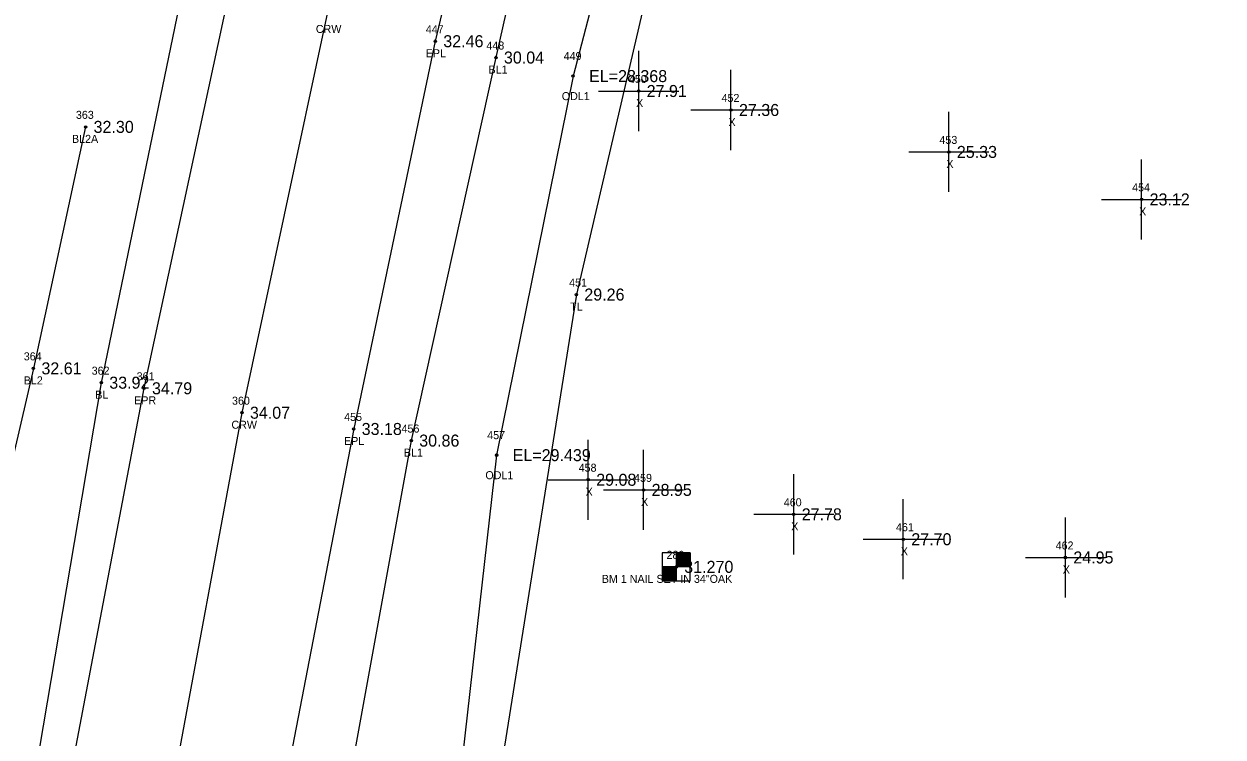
# Model space of a CAD drawing. Extents: x 2042211 to 2045853, y 303080 to 309569.
# Drawn here: x 2042849.9 to 2042999.7, y 307682.5 to 307771.5 of the extents above; entities that cross this region are included whole.
import ezdxf

# ---------------------------------------------------------------- set-up
doc = ezdxf.new("R2010")
doc.units = 0
for name, color, linetype in [('BR_500YR_SCOUR', 7, 'Continuous'), ('RD_DTM_BkLn1', 7, 'Continuous'), ('RD_DTM_BkLn_txCode', 7, 'Continuous'), ('RD_EX_H2O', 7, 'Continuous'), ('RD_EX_H2O_txCode', 7, 'Continuous'), ('RD_EX_Misc', 7, 'Continuous'), ('RD_EX_Misc_txCode', 7, 'Continuous'), ('RD_EX_Road', 7, 'Continuous'), ('RD_EX_Road_txCode', 7, 'Continuous'), ('RD_EX_TX_H2O_ELEV', 7, 'Continuous'), ('RD_EX_TX_Misc_ELEV', 7, 'Continuous'), ('RD_EX_TX_Road_ELEV', 7, 'Continuous'), ('RD_EX_TX_VEG_ELEV', 7, 'Continuous'), ('RD_EX_VEG_txCode', 7, 'Continuous'), ('RD_HC_Survey_ELEV', 7, 'Continuous'), ('RD_HC_Survey_txCode', 7, 'Continuous'), ('RD_SMD_Locator', 7, 'Continuous')]:
    doc.layers.add(name, color=color, linetype=linetype)

msp = doc.modelspace()

# ---------------------------------------------------------------- linework, layer by layer
at = {"layer": 'BR_500YR_SCOUR'}
for p, q in [((2042931.41, 307705.48), (2042931.41, 307701.98)), ((2042931.43, 307705.48), (2042931.43, 307703.73)), ((2042931.45, 307705.48), (2042931.45, 307703.73)), ((2042931.48, 307705.48), (2042931.48, 307703.73)), ((2042931.5, 307705.48), (2042931.5, 307703.73)), ((2042931.53, 307705.48), (2042931.53, 307703.73)), ((2042931.55, 307705.48), (2042931.55, 307703.73)), ((2042931.58, 307705.48), (2042931.58, 307703.73)), ((2042931.6, 307705.48), (2042931.6, 307703.73)), ((2042931.63, 307705.48), (2042931.63, 307703.73)), ((2042931.65, 307705.48), (2042931.65, 307703.73)), ((2042931.68, 307705.48), (2042931.68, 307703.73)), ((2042931.7, 307705.48), (2042931.7, 307703.73)), ((2042931.72, 307705.48), (2042931.72, 307703.73)), ((2042931.75, 307705.48), (2042931.75, 307703.73)), ((2042931.77, 307705.48), (2042931.77, 307703.73)), ((2042931.8, 307705.48), (2042931.8, 307703.73)), ((2042931.82, 307705.48), (2042931.82, 307703.73)), ((2042931.85, 307705.48), (2042931.85, 307703.73)), ((2042931.87, 307705.48), (2042931.87, 307703.73)), ((2042931.9, 307705.48), (2042931.9, 307703.73)), ((2042931.92, 307705.48), (2042931.92, 307703.73)), ((2042931.95, 307705.48), (2042931.95, 307703.73)), ((2042931.97, 307705.48), (2042931.97, 307703.73)), ((2042932, 307705.48), (2042932, 307703.73)), ((2042932.02, 307705.48), (2042932.02, 307703.73)), ((2042932.05, 307705.48), (2042932.05, 307703.73)), ((2042932.07, 307705.48), (2042932.07, 307703.73)), ((2042932.1, 307705.48), (2042932.1, 307703.73)), ((2042932.12, 307705.48), (2042932.12, 307703.73)), ((2042932.15, 307705.48), (2042932.15, 307703.73)), ((2042932.17, 307705.48), (2042932.17, 307703.73)), ((2042932.19, 307705.48), (2042932.19, 307703.73)), ((2042932.22, 307705.48), (2042932.22, 307703.73)), ((2042932.24, 307705.48), (2042932.24, 307703.73)), ((2042932.27, 307705.48), (2042932.27, 307703.73)), ((2042932.29, 307705.48), (2042932.29, 307703.73)), ((2042932.32, 307705.48), (2042932.32, 307703.73)), ((2042932.34, 307705.48), (2042932.34, 307703.73)), ((2042932.37, 307705.48), (2042932.37, 307703.73)), ((2042932.39, 307705.48), (2042932.39, 307703.73)), ((2042932.42, 307705.48), (2042932.42, 307703.73)), ((2042932.44, 307705.48), (2042932.44, 307703.73)), ((2042932.47, 307705.48), (2042932.47, 307703.73)), ((2042932.49, 307705.48), (2042932.49, 307703.73)), ((2042932.52, 307705.48), (2042932.52, 307703.73)), ((2042932.54, 307705.48), (2042932.54, 307703.73)), ((2042932.57, 307705.48), (2042932.57, 307703.73)), ((2042932.59, 307705.48), (2042932.59, 307703.73)), ((2042932.62, 307705.48), (2042932.62, 307703.73)), ((2042932.64, 307705.48), (2042932.64, 307703.73)), ((2042932.67, 307705.48), (2042932.67, 307703.73)), ((2042932.69, 307705.48), (2042932.69, 307703.73)), ((2042932.71, 307705.48), (2042932.71, 307703.73)), ((2042932.74, 307705.48), (2042932.74, 307703.73)), ((2042932.76, 307705.48), (2042932.76, 307703.73)), ((2042932.79, 307705.48), (2042932.79, 307703.73)), ((2042932.81, 307705.48), (2042932.81, 307703.73)), ((2042932.84, 307705.48), (2042932.84, 307703.73)), ((2042932.86, 307705.48), (2042932.86, 307703.73)), ((2042932.89, 307705.48), (2042932.89, 307703.73)), ((2042932.91, 307705.48), (2042932.91, 307703.73)), ((2042932.94, 307705.48), (2042932.94, 307703.73)), ((2042932.96, 307705.48), (2042932.96, 307703.73)), ((2042932.99, 307705.48), (2042932.99, 307703.73)), ((2042933.01, 307705.48), (2042933.01, 307703.73)), ((2042933.04, 307705.48), (2042933.04, 307703.73)), ((2042933.06, 307705.48), (2042933.06, 307703.73)), ((2042933.09, 307705.48), (2042933.09, 307703.73)), ((2042933.11, 307705.48), (2042933.11, 307703.73)), ((2042933.14, 307705.48), (2042933.14, 307703.73)), ((2042933.16, 307703.73), (2042929.66, 307703.73)), ((2042929.66, 307703.73), (2042929.66, 307701.98)), ((2042929.68, 307703.73), (2042929.68, 307701.98)), ((2042929.71, 307703.73), (2042929.71, 307701.98)), ((2042929.73, 307703.73), (2042929.73, 307701.98)), ((2042929.76, 307703.73), (2042929.76, 307701.98)), ((2042929.78, 307703.73), (2042929.78, 307701.98)), ((2042929.81, 307703.73), (2042929.81, 307701.98)), ((2042929.83, 307703.73), (2042929.83, 307701.98)), ((2042929.86, 307703.73), (2042929.86, 307701.98)), ((2042929.88, 307703.73), (2042929.88, 307701.98)), ((2042929.91, 307703.73), (2042929.91, 307701.98)), ((2042929.93, 307703.73), (2042929.93, 307701.98)), ((2042929.96, 307703.73), (2042929.96, 307701.98)), ((2042929.98, 307703.73), (2042929.98, 307701.98)), ((2042930.01, 307703.73), (2042930.01, 307701.98)), ((2042930.03, 307703.73), (2042930.03, 307701.98)), ((2042930.06, 307703.73), (2042930.06, 307701.98)), ((2042930.08, 307703.73), (2042930.08, 307701.98)), ((2042930.11, 307703.73), (2042930.11, 307701.98)), ((2042930.13, 307703.73), (2042930.13, 307701.98)), ((2042930.16, 307703.73), (2042930.16, 307701.98)), ((2042930.18, 307703.73), (2042930.18, 307701.98)), ((2042930.2, 307703.73), (2042930.2, 307701.98)), ((2042930.23, 307703.73), (2042930.23, 307701.98)), ((2042930.25, 307703.73), (2042930.25, 307701.98)), ((2042930.28, 307703.73), (2042930.28, 307701.98)), ((2042930.3, 307703.73), (2042930.3, 307701.98)), ((2042930.33, 307703.73), (2042930.33, 307701.98)), ((2042930.35, 307703.73), (2042930.35, 307701.98)), ((2042930.38, 307703.73), (2042930.38, 307701.98)), ((2042930.4, 307703.73), (2042930.4, 307701.98)), ((2042930.43, 307703.73), (2042930.43, 307701.98)), ((2042930.45, 307703.73), (2042930.45, 307701.98)), ((2042930.48, 307703.73), (2042930.48, 307701.98)), ((2042930.5, 307703.73), (2042930.5, 307701.98)), ((2042930.53, 307703.73), (2042930.53, 307701.98)), ((2042930.55, 307703.73), (2042930.55, 307701.98)), ((2042930.58, 307703.73), (2042930.58, 307701.98)), ((2042930.6, 307703.73), (2042930.6, 307701.98)), ((2042930.63, 307703.73), (2042930.63, 307701.98)), ((2042930.65, 307703.73), (2042930.65, 307701.98)), ((2042930.67, 307703.73), (2042930.67, 307701.98)), ((2042930.7, 307703.73), (2042930.7, 307701.98)), ((2042930.72, 307703.73), (2042930.72, 307701.98)), ((2042930.75, 307703.73), (2042930.75, 307701.98)), ((2042930.77, 307703.73), (2042930.77, 307701.98)), ((2042930.8, 307703.73), (2042930.8, 307701.98)), ((2042930.82, 307703.73), (2042930.82, 307701.98)), ((2042930.85, 307703.73), (2042930.85, 307701.98)), ((2042930.87, 307703.73), (2042930.87, 307701.98)), ((2042930.9, 307703.73), (2042930.9, 307701.98)), ((2042930.92, 307703.73), (2042930.92, 307701.98)), ((2042930.95, 307703.73), (2042930.95, 307701.98)), ((2042930.97, 307703.73), (2042930.97, 307701.98)), ((2042931, 307703.73), (2042931, 307701.98)), ((2042931.02, 307703.73), (2042931.02, 307701.98)), ((2042931.05, 307703.73), (2042931.05, 307701.98)), ((2042931.07, 307703.73), (2042931.07, 307701.98)), ((2042931.1, 307703.73), (2042931.1, 307701.98)), ((2042931.12, 307703.73), (2042931.12, 307701.98)), ((2042931.15, 307703.73), (2042931.15, 307701.98)), ((2042931.17, 307703.73), (2042931.17, 307701.98)), ((2042931.19, 307703.73), (2042931.19, 307701.98)), ((2042931.22, 307703.73), (2042931.22, 307701.98)), ((2042931.24, 307703.73), (2042931.24, 307701.98)), ((2042931.27, 307703.73), (2042931.27, 307701.98)), ((2042931.29, 307703.73), (2042931.29, 307701.98)), ((2042931.32, 307703.73), (2042931.32, 307701.98)), ((2042931.34, 307703.73), (2042931.34, 307701.98)), ((2042931.37, 307703.73), (2042931.37, 307701.98)), ((2042931.39, 307703.73), (2042931.39, 307701.98))]:
    msp.add_line(p, q, dxfattribs=at)
msp.add_lwpolyline([(2043048.7, 308112.2), (2043032.62, 308087.68), (2043027.55, 308080.82), (2043013.5, 308043.09), (2042994.71, 307997.39), (2042983.47, 307967.75), (2042952.97, 307870.73), (2042935.66, 307809.47), (2042918.92, 307737.74), (2042902.79, 307636.4), (2042902.54, 307635.29), (2042891, 307519.21), (2042885.61, 307482.85), (2042881.1, 307379.92), (2042880.44, 307351.7), (2042880.19, 307284.9)], dxfattribs=at)
msp.add_lwpolyline([(2042933.16, 307705.48), (2042929.66, 307705.48), (2042929.66, 307701.98), (2042933.16, 307701.98)], close=True, dxfattribs=at)
for centre in [(2042918.92, 307737.74), (2042931.41, 307703.73)]:
    msp.add_circle(centre, 0.15, dxfattribs=at)
at = {"layer": 'RD_DTM_BkLn1'}
for points in [[(2043161.13, 308408.97), (2043133.81, 308366.92), (2043082.92, 308281.6), (2043059.61, 308238.25), (2043036.96, 308193.55), (2043015.53, 308147.97), (2042995.29, 308102.87), (2042976.3, 308056.87), (2042958.8, 308010.83), (2042942.32, 307963.75), (2042927.06, 307916.53), (2042912.57, 307868.35), (2042899.47, 307820.61), (2042887.68, 307772.41), (2042877.12, 307722.98), (2042868.22, 307675.1), (2042860.12, 307626.05), (2042853.34, 307576.87), (2042847.77, 307527.39), (2042843.87, 307477.74), (2042841.31, 307428.69), (2042840.04, 307379.1), (2042839.81, 307329.37), (2042840.93, 307280.46)], [(2043084.04, 308249.78), (2043074.97, 308230.46), (2043053.22, 308185.62), (2043031.61, 308140.82), (2043017.56, 308093.82), (2042997.77, 308049.45), (2042978.41, 308004.57), (2042961.32, 307957.89), (2042945.16, 307911.22), (2042932.79, 307863.05), (2042919.73, 307815.78), (2042908.87, 307767.34), (2042898.28, 307719.5), (2042889.52, 307671.44), (2042882.14, 307623.35), (2042877.76, 307594.41)], [(2042869.74, 307776.07), (2042859.54, 307726.73), (2042851.31, 307678.22), (2042843.92, 307628.21), (2042836.41, 307578.73), (2042830.84, 307528.85), (2042827.5, 307478.96), (2042824.99, 307429.39), (2042821.8, 307378.88), (2042823.15, 307329.29), (2042823.59, 307279.35)], [(2042857.58, 307758.68), (2042851.06, 307728.52), (2042839.84, 307680.16), (2042833.97, 307629.9), (2042821.17, 307580.23), (2042822.56, 307529.56), (2042819.57, 307479.56), (2042814.78, 307429.4), (2042809.83, 307378.82), (2042809.03, 307329.14)]]:
    msp.add_lwpolyline(points, dxfattribs=at)
at = {"layer": 'RD_EX_H2O'}
msp.add_lwpolyline([(2042954.71, 307908), (2042941.87, 307861.24), (2042931.11, 307813.3), (2042918.51, 307765.02), (2042908.96, 307717.68), (2042903.47, 307669.35), (2042893.06, 307622.27), (2042888.33, 307593.93)], dxfattribs=at)
at = {"layer": 'RD_EX_Misc'}
for p, q in [((2042926.71, 307758.16), (2042926.71, 307768.16)), ((2042938.25, 307755.79), (2042938.25, 307765.79)), ((2042921.71, 307763.16), (2042931.71, 307763.16)), ((2042933.25, 307760.79), (2042943.25, 307760.79)), ((2042965.48, 307750.55), (2042965.48, 307760.55)), ((2042960.48, 307755.55), (2042970.48, 307755.55)), ((2042989.57, 307744.62), (2042989.57, 307754.62)), ((2042984.57, 307749.62), (2042994.57, 307749.62)), ((2042920.4, 307709.61), (2042920.4, 307719.61)), ((2042927.33, 307708.34), (2042927.33, 307718.34)), ((2042915.4, 307714.61), (2042925.4, 307714.61)), ((2042946.09, 307705.29), (2042946.09, 307715.29)), ((2042922.33, 307713.34), (2042932.33, 307713.34)), ((2042959.79, 307702.18), (2042959.79, 307712.18)), ((2042941.09, 307710.29), (2042951.09, 307710.29)), ((2042980.04, 307699.9), (2042980.04, 307709.9)), ((2042954.79, 307707.18), (2042964.79, 307707.18)), ((2042975.04, 307704.9), (2042985.04, 307704.9))]:
    msp.add_line(p, q, dxfattribs=at)
at = {"layer": 'RD_EX_Road'}
for points in [[(2042912.69, 307817.39), (2042901.29, 307769.38), (2042891.09, 307720.95), (2042881.8, 307672.88), (2042874.23, 307624.44), (2042867.25, 307575.38), (2042861.55, 307525.78), (2042857.62, 307475.83), (2042855.03, 307427.78), (2042853.64, 307379.19), (2042853.31, 307329.44), (2042854.43, 307281.38)], [(2042875.38, 307775.02), (2042864.88, 307726.03), (2042855.57, 307677.22), (2042847.6, 307627.85), (2042840.73, 307578.32), (2042835.07, 307528.58), (2042830.98, 307478.6), (2042828.36, 307428.87), (2042826.99, 307378.91), (2042826.88, 307329.29), (2042828.01, 307279.82)]]:
    msp.add_lwpolyline(points, dxfattribs=at)
at = {"layer": 'RD_SMD_Locator'}
for centre in [(2042901.29, 307769.38), (2042908.87, 307767.34), (2042918.51, 307765.02), (2042926.71, 307763.16), (2042938.25, 307760.79), (2042857.58, 307758.68), (2042965.48, 307755.55), (2042989.57, 307749.62), (2042851.06, 307728.52), (2042859.54, 307726.73), (2042864.88, 307726.03), (2042877.12, 307722.98), (2042891.09, 307720.95), (2042898.28, 307719.5), (2042908.96, 307717.68), (2042920.4, 307714.61), (2042927.33, 307713.34), (2042946.09, 307710.29), (2042959.79, 307707.18), (2042980.04, 307704.9)]:
    msp.add_circle(centre, 0.15, dxfattribs=at)

# ---------------------------------------------------------------- texts
at = {"layer": 'RD_DTM_BkLn_txCode'}
for s, p in [('448', (2042907.68, 307768.34)), ('BL1', (2042907.94, 307765.34)), ('363', (2042856.37, 307759.68)), ('BL2A', (2042855.88, 307756.68)), ('364', (2042849.85, 307729.52)), ('362', (2042858.34, 307727.73)), ('BL2', (2042849.85, 307726.52)), ('BL', (2042858.79, 307724.73)), ('456', (2042897.07, 307720.5)), ('BL1', (2042897.36, 307717.5))]:
    msp.add_text(s, height=1, dxfattribs=at).set_placement(p)
at = {"layer": 'RD_EX_H2O_txCode'}
for s, p in [('449', (2042917.33, 307767.02)), ('ODL1', (2042917.1, 307762.02)), ('457', (2042907.78, 307719.68)), ('ODL1', (2042907.55, 307714.68))]:
    msp.add_text(s, height=1, dxfattribs=at).set_placement(p)
at = {"layer": 'RD_EX_Misc_txCode'}
for s, p in [('450', (2042925.49, 307764.16)), ('452', (2042937.07, 307761.79)), ('X', (2042926.39, 307761.16)), ('X', (2042937.94, 307758.79)), ('453', (2042964.3, 307756.55)), ('X', (2042965.17, 307753.55)), ('454', (2042988.39, 307750.62)), ('X', (2042989.26, 307747.62)), ('458', (2042919.21, 307715.61)), ('459', (2042926.14, 307714.34)), ('X', (2042920.08, 307712.61)), ('X', (2042927.01, 307711.34)), ('460', (2042944.85, 307711.29)), ('X', (2042945.78, 307708.29)), ('461', (2042958.87, 307708.18)), ('X', (2042959.48, 307705.18)), ('462', (2042978.83, 307705.9)), ('X', (2042979.72, 307702.9))]:
    msp.add_text(s, height=1, dxfattribs=at).set_placement(p)
at = {"layer": 'RD_EX_Road_txCode'}
for s, p in [('447', (2042900.11, 307770.38)), ('EPL', (2042900.09, 307767.38)), ('361', (2042863.96, 307727.03)), ('EPR', (2042863.65, 307724.03)), ('455', (2042889.9, 307721.95)), ('EPL', (2042889.88, 307718.95))]:
    msp.add_text(s, height=1, dxfattribs=at).set_placement(p)
at = {"layer": 'RD_EX_TX_H2O_ELEV'}
for s, p in [('EL=28.368', (2042920.51, 307764.27)), ('EL=29.439', (2042910.96, 307716.93))]:
    msp.add_text(s, height=1.5, dxfattribs=at).set_placement(p)
at = {"layer": 'RD_EX_TX_Misc_ELEV'}
for s, p in [('30.04', (2042909.87, 307766.59)), ('27.91', (2042927.71, 307762.41)), ('27.36', (2042939.25, 307760.04)), ('32.30', (2042858.58, 307757.93)), ('25.33', (2042966.48, 307754.8)), ('23.12', (2042990.57, 307748.87)), ('32.61', (2042852.06, 307727.77)), ('33.92', (2042860.54, 307725.98)), ('30.86', (2042899.28, 307718.75)), ('29.08', (2042921.4, 307713.86)), ('28.95', (2042928.33, 307712.59)), ('27.78', (2042947.09, 307709.54)), ('27.70', (2042960.79, 307706.43)), ('24.95', (2042981.04, 307704.15))]:
    msp.add_text(s, height=1.5, dxfattribs=at).set_placement(p)
at = {"layer": 'RD_EX_TX_Road_ELEV'}
for s, p in [('32.46', (2042902.29, 307768.63)), ('34.79', (2042865.88, 307725.28)), ('33.18', (2042892.09, 307720.2))]:
    msp.add_text(s, height=1.5, dxfattribs=at).set_placement(p)
at = {"layer": 'RD_EX_TX_VEG_ELEV'}
msp.add_text('29.26', height=1.5, dxfattribs=at).set_placement((2042919.92, 307736.99))
at = {"layer": 'RD_EX_VEG_txCode'}
for s, p in [('451', (2042918.02, 307738.74)), ('TL', (2042918.15, 307735.74))]:
    msp.add_text(s, height=1, dxfattribs=at).set_placement(p)
at = {"layer": 'RD_HC_Survey_ELEV'}
for s, p in [('34.07', (2042878.12, 307722.23)), ('31.270', (2042932.41, 307702.98))]:
    msp.add_text(s, height=1.5, dxfattribs=at).set_placement(p)
at = {"layer": 'RD_HC_Survey_txCode'}
for s, p in [('CRW', (2042886.36, 307770.41)), ('360', (2042875.88, 307723.98)), ('CRW', (2042875.81, 307720.98)), ('280', (2042930.19, 307704.73)), ('BM 1 NAIL SET IN 34"OAK', (2042922.1, 307701.73))]:
    msp.add_text(s, height=1, dxfattribs=at).set_placement(p)

doc.saveas('drawing.dxf')
